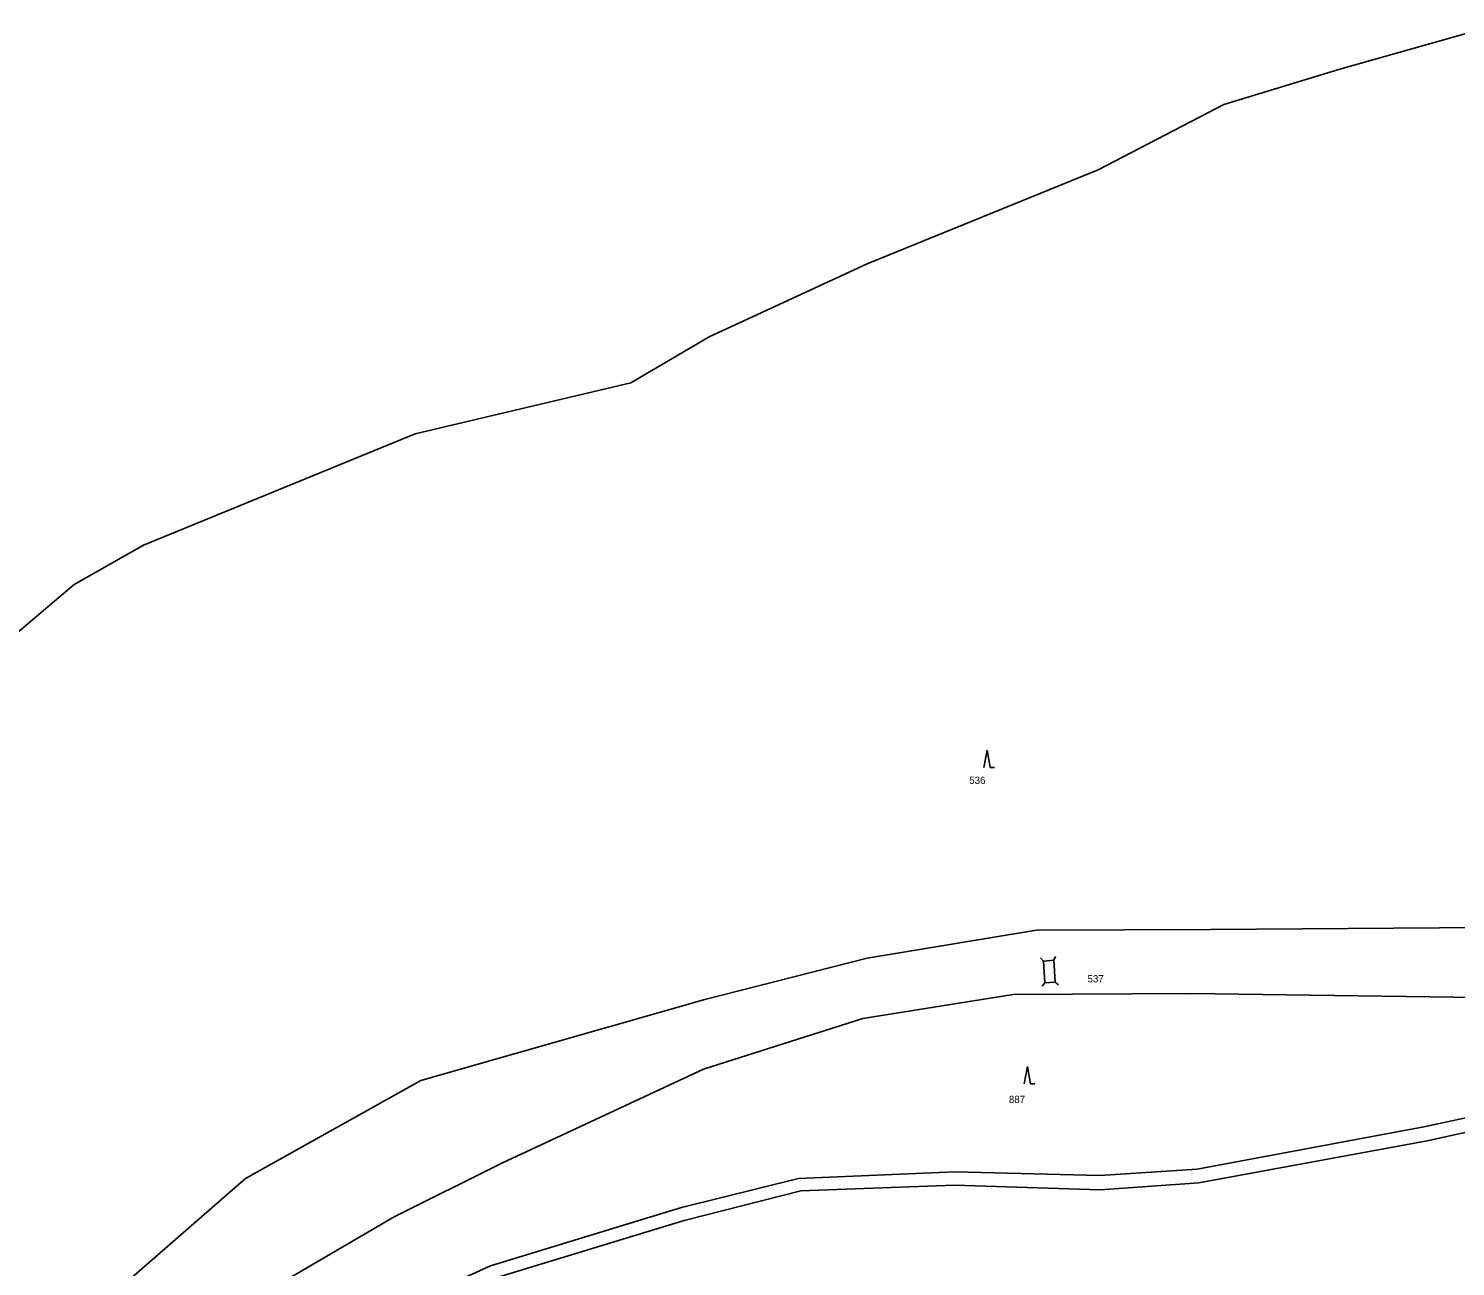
# Model space of a CAD drawing. Extents: x -520431 to -517205, y -1075927 to -1074013.
# Drawn here: x -519978.1 to -519643.5, y -1075095.5 to -1074805.4 of the extents above; entities that cross this region are included whole.
import ezdxf

# ---------------------------------------------------------------- set-up
doc = ezdxf.new("R2010")
doc.units = 0
for name, color, linetype in [('Hranice parcel', 7, 'Continuous'), ('Parcelní čísla', 7, 'Continuous'), ('Vnitřní kresba', 7, 'Continuous'), ('Vrstva 54', 7, 'Continuous'), ('Značky kultur', 7, 'Continuous')]:
    doc.layers.add(name, color=color, linetype=linetype)

msp = doc.modelspace()

# ---------------------------------------------------------------- linework, layer by layer
at = {"layer": 'Hranice parcel'}
for points in [[(-519636.88, -1074805.37), (-519670.61, -1074814.92), (-519697.8, -1074823.14)], [(-519697.8, -1074823.14), (-519727.29, -1074838.48), (-519781.47, -1074860.53), (-519818.49, -1074877.62)], [(-519818.49, -1074877.62), (-519836.86, -1074888.38), (-519887.49, -1074900.33), (-519951.19, -1074926.47)], [(-519924.37, -1075102.58), (-519892.38, -1075083.85), (-519867.1, -1075071.27), (-519819.84, -1075049.28), (-519782.45, -1075037.35), (-519747.25, -1075031.75), (-519705.46, -1075031.49), (-519632.74, -1075032.56), (-519553.06, -1075033.29), (-519504.34, -1075033.24), (-519467.55, -1075032.52), (-519378.37, -1075033.84), (-519288.33, -1075035.21), (-519275.81, -1075034.42), (-519271.08, -1075034.12), (-519267.29, -1075033.89), (-519226.23, -1075021.14), (-519174.38, -1075001.72), (-519158.26, -1074993.34), (-519124.51, -1074973.19), (-519104.71, -1074961.98), (-519067.92, -1074936.75), (-519042.21, -1074912.15), (-519022.03, -1074880.42)], [(-519951.19, -1074926.47), (-519967.4, -1074935.67), (-519990.65, -1074955.24)], [(-519973.97, -1075115.61), (-519927.27, -1075074.86), (-519886.14, -1075051.93), (-519819.53, -1075032.9), (-519781.46, -1075023.27), (-519741.74, -1075016.65), (-519700.87, -1075016.53), (-519625.74, -1075016)]]:
    msp.add_lwpolyline(points, dxfattribs=at)
at = {"layer": 'Vnitřní kresba'}
for p, q in [((-519737.3, -1075022.83), (-519737.71, -1075023.74)), ((-519740.82, -1075023.2), (-519740.12, -1075023.92)), ((-519740.12, -1075023.92), (-519737.71, -1075023.74)), ((-519740.12, -1075023.92), (-519739.84, -1075029)), ((-519737.71, -1075023.74), (-519737.38, -1075028.86)), ((-519740.43, -1075029.81), (-519739.84, -1075029)), ((-519739.84, -1075029), (-519737.38, -1075028.86)), ((-519736.59, -1075029.48), (-519737.38, -1075028.86)), ((-519650.93, -1075062.74), (-519599.48, -1075051.71)), ((-519598.84, -1075054.68), (-519650.16, -1075066.06)), ((-519704.06, -1075072.67), (-519650.93, -1075062.74)), ((-519650.16, -1075066.06), (-519703.68, -1075075.93)), ((-519726.94, -1075074.17), (-519704.06, -1075072.67)), ((-519825.02, -1075081.66), (-519797.54, -1075074.88)), ((-519797.54, -1075074.88), (-519760.88, -1075073.29)), ((-519761, -1075076.43), (-519797.05, -1075077.74)), ((-519726.83, -1075077.52), (-519761, -1075076.43)), ((-519760.88, -1075073.29), (-519726.94, -1075074.17)), ((-519703.68, -1075075.93), (-519726.83, -1075077.52)), ((-519797.05, -1075077.74), (-519824.39, -1075084.7)), ((-519869.8, -1075095.33), (-519825.02, -1075081.66)), ((-519824.39, -1075084.7), (-519868.78, -1075098.27)), ((-519900.85, -1075109.38), (-519869.8, -1075095.33))]:
    msp.add_line(p, q, dxfattribs=at)
at = {"layer": 'Vrstva 54'}
for points in [[(-519022.03, -1074880.42), (-519042.21, -1074912.15), (-519067.92, -1074936.75), (-519104.71, -1074961.98), (-519158.26, -1074993.34), (-519174.38, -1075001.72), (-519226.23, -1075021.14), (-519267.29, -1075033.89), (-519271.08, -1075034.12), (-519275.81, -1075034.42), (-519288.33, -1075035.21), (-519378.37, -1075033.84), (-519467.55, -1075032.52), (-519504.34, -1075033.24), (-519553.06, -1075033.29), (-519632.74, -1075032.56), (-519705.46, -1075031.49), (-519747.25, -1075031.75), (-519782.45, -1075037.35), (-519819.84, -1075049.28), (-519867.1, -1075071.27), (-519892.38, -1075083.85), (-519924.37, -1075102.58)], [(-519973.97, -1075115.61), (-519927.27, -1075074.86), (-519886.14, -1075051.93), (-519819.53, -1075032.9), (-519781.46, -1075023.27), (-519741.74, -1075016.65), (-519700.87, -1075016.53), (-519625.74, -1075016)]]:
    msp.add_lwpolyline(points, dxfattribs=at)
at = {"layer": 'Značky kultur'}
for p, q in [((-519753.34, -1074974.53), (-519754.09, -1074978.53)), ((-519752.59, -1074978.53), (-519753.34, -1074974.53)), ((-519752.59, -1074978.53), (-519751.59, -1074978.53)), ((-519743.9, -1075048.67), (-519744.65, -1075052.67)), ((-519743.15, -1075052.67), (-519743.9, -1075048.67)), ((-519743.15, -1075052.67), (-519742.15, -1075052.67))]:
    msp.add_line(p, q, dxfattribs=at)

# ---------------------------------------------------------------- texts
at = {"layer": 'Parcelní čísla'}
for s, p in [('536', (-519757.53, -1074982.41)), ('537', (-519729.79, -1075028.93)), ('887', (-519748.23, -1075057.19))]:
    msp.add_text(s, height=1.7, dxfattribs=at).set_placement(p)

doc.saveas('drawing.dxf')
